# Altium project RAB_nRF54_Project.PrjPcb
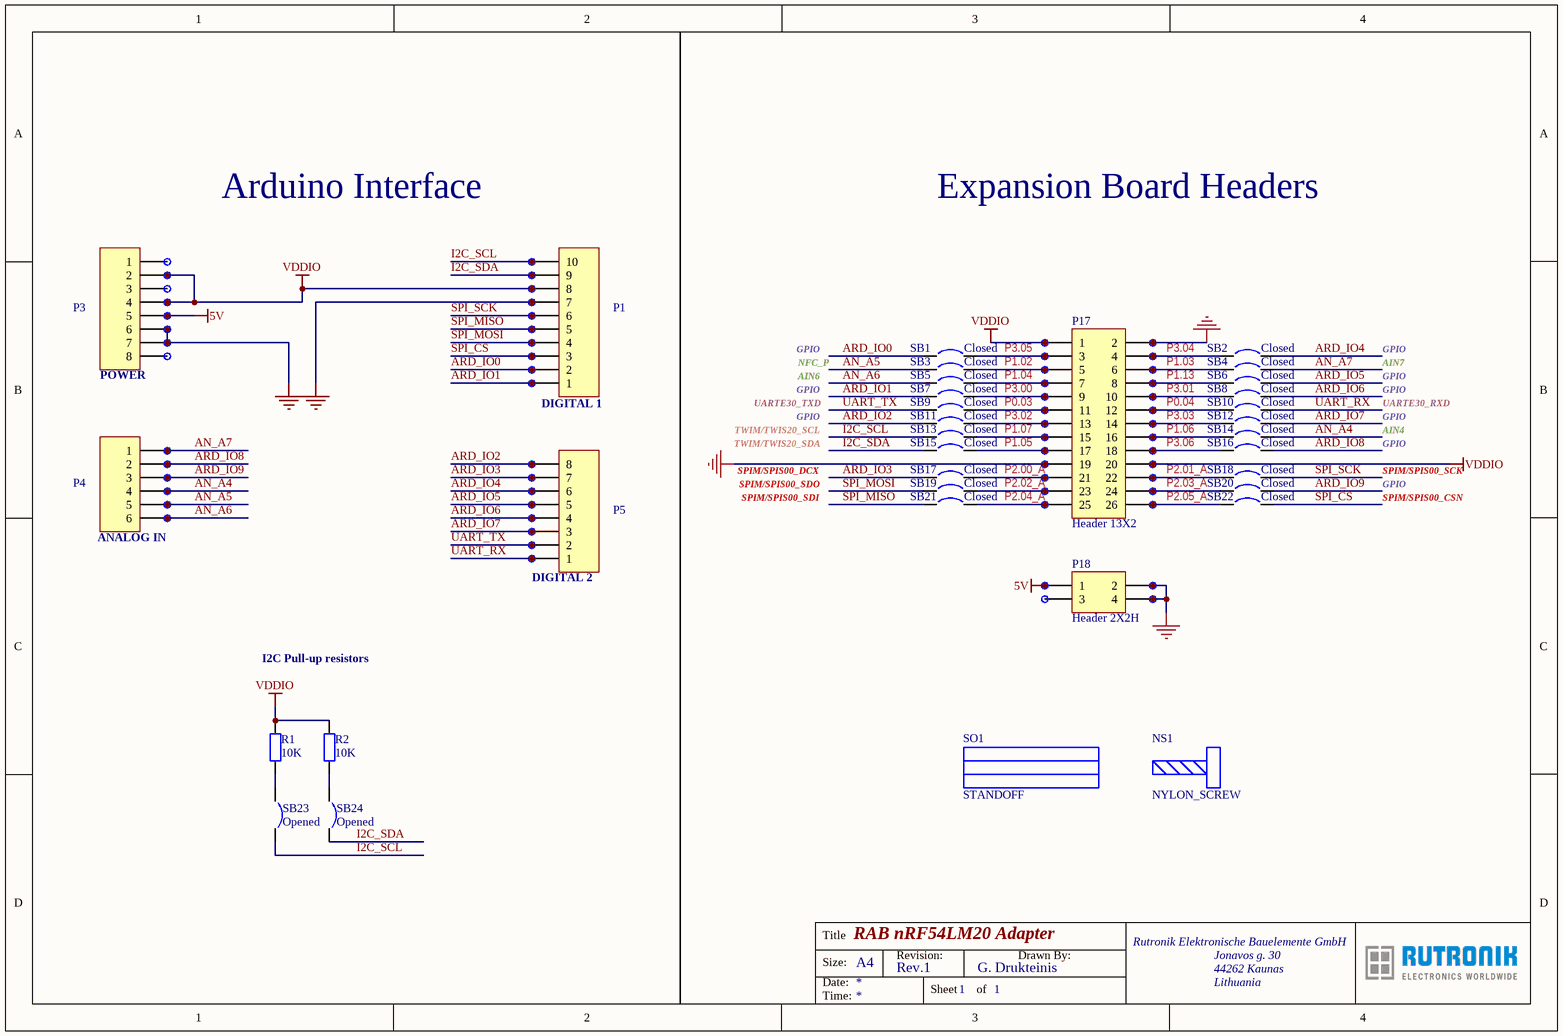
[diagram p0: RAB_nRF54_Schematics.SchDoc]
1 sheet, 96 parts. Net scope: global (net labels, ports and power ports of the same name join across sheets).
Board file: RAB-nRF54 PCB.PcbDoc

## Sheet RAB_nRF54_Schematics.SchDoc: RAB nRF54LM20 Adapter
size A4; DrawnBy: G. Drukteinis; Organization: Rutronik Elektronische Bauelemente GmbH; Address1: Jonavos g. 30; Address2: 44262 Kaunas; Address3: Lithuania; Revision: Rev.1; SheetNumber: 1; SheetTotal: 1

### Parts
J1  pin_tht  [PIN_THT]  (value not drawn)  (no BOM)
J2  pin_tht  [PIN_THT]  (value not drawn)  (no BOM)
J3  pin_tht  [PIN_THT]  (value not drawn)  (no BOM)
J4  pin_tht  [PIN_THT]  (value not drawn)  (no BOM)
J5  pin_tht  [PIN_THT]  (value not drawn)  (no BOM)
J6  pin_tht  [PIN_THT]  (value not drawn)  (no BOM)
J7  pin_tht  [PIN_THT]  (value not drawn)  (no BOM)
J8  pin_tht  [PIN_THT]  (value not drawn)  (no BOM)
J9  pin_tht  [PIN_THT]  (value not drawn)  (no BOM)
J10  pin_tht  [PIN_THT]  (value not drawn)  (no BOM)
J11  pin_tht  [PIN_THT]  (value not drawn)  (no BOM)
J12  pin_tht  [PIN_THT]  (value not drawn)  (no BOM)
J13  pin_tht  [PIN_THT]  (value not drawn)  (no BOM)
J14  pin_tht  [PIN_THT]  (value not drawn)  (no BOM)
J15  pin_tht  [PIN_THT]  (value not drawn)  (no BOM)
J16  pin_tht  [PIN_THT]  (value not drawn)  (no BOM)
J17  pin_tht  [PIN_THT]  (value not drawn)  (no BOM)
J18  pin_tht  [PIN_THT]  (value not drawn)  (no BOM)
J19  pin_tht  [PIN_THT]  (value not drawn)  (no BOM)
J20  pin_tht  [PIN_THT]  (value not drawn)  (no BOM)
J21  pin_tht  [PIN_THT]  (value not drawn)  (no BOM)
J22  pin_tht  [PIN_THT]  (value not drawn)  (no BOM)
J23  pin_tht  [PIN_THT]  (value not drawn)  (no BOM)
J24  pin_tht  [PIN_THT]  (value not drawn)  (no BOM)
J25  pin_tht  [PIN_THT]  (value not drawn)  (no BOM)
J26  pin_tht  [PIN_THT]  (value not drawn)  (no BOM)
J27  pin_tht  [PIN_THT]  (value not drawn)  (no BOM)
J28  pin_tht  [PIN_THT]  (value not drawn)  (no BOM)
J29  pin_tht  [PIN_THT]  (value not drawn)  (no BOM)
J30  pin_tht  [PIN_THT]  (value not drawn)  (no BOM)
J31  pin_tht  [PIN_THT]  (value not drawn)  (no BOM)
J32  pin_tht  [PIN_THT]  (value not drawn)  (no BOM)
J33  pin_tht  [PIN_THT]  (value not drawn)  (no BOM)
J34  pin_tht  [PIN_THT]  (value not drawn)  (no BOM)
J35  pin_tht  [PIN_THT]  (value not drawn)  (no BOM)
J36  pin_tht  [PIN_THT]  (value not drawn)  (no BOM)
J37  pin_tht  [PIN_THT]  (value not drawn)  (no BOM)
J38  pin_tht  [PIN_THT]  (value not drawn)  (no BOM)
J39  pin_tht  [PIN_THT]  (value not drawn)  (no BOM)
J40  pin_tht  [PIN_THT]  (value not drawn)  (no BOM)
J41  pin_tht  [PIN_THT]  (value not drawn)  (no BOM)
J42  pin_tht  [PIN_THT]  (value not drawn)  (no BOM)
J43  pin_tht  [PIN_THT]  (value not drawn)  (no BOM)
J44  pin_tht  [PIN_THT]  (value not drawn)  (no BOM)
J45  pin_tht  [PIN_THT]  (value not drawn)  (no BOM)
J46  pin_tht  [PIN_THT]  (value not drawn)  (no BOM)
J47  pin_tht  [PIN_THT]  (value not drawn)  (no BOM)
J48  pin_tht  [PIN_THT]  (value not drawn)  (no BOM)
J49  pin_tht  [PIN_THT]  (value not drawn)  (no BOM)
J50  pin_tht  [PIN_THT]  (value not drawn)  (no BOM)
J51  pin_tht  [PIN_THT]  (value not drawn)  (no BOM)
J52  pin_tht  [PIN_THT]  (value not drawn)  (no BOM)
J53  pin_tht  [PIN_THT]  (value not drawn)  (no BOM)
J54  pin_tht  [PIN_THT]  (value not drawn)  (no BOM)
J55  pin_tht  [PIN_THT]  (value not drawn)  (no BOM)
J56  pin_tht  [PIN_THT]  (value not drawn)  (no BOM)
J57  pin_tht  [PIN_THT]  (value not drawn)  (no BOM)
J58  pin_tht  [PIN_THT]  (value not drawn)  (no BOM)
J59  pin_tht  [PIN_THT]  (value not drawn)  (no BOM)
J60  pin_tht  [PIN_THT]  (value not drawn)  (no BOM)
J61  pin_tht  [PIN_THT]  (value not drawn)  (no BOM)
J62  pin_tht  [PIN_THT]  (value not drawn)  (no BOM)
NS1  NYLON_SCREW  [29311]
P1  DIGITAL 1  [Arduino_HDR1X10_main]
P3  POWER  [rduino_HDR1X8_main]
P4  ANALOG IN  [Arduino_HDR1X6_main]
P5  DIGITAL 2  [rduino_HDR1X8_main]
P17  Header 13X2  [RECEPTACLE_2x13_2.54_5x8.5]
P18  Header 2X2H  [RECEPTACLE_2x2_2.54_5x8.5]
R1  value 10K  [R0402]  (hidden comment: Res2)
R2  value 10K  [R0402]  (hidden comment: Res2)
SB1  Closed  [SB_0402]
SB2  Closed  [SB_0402]
SB3  Closed  [SB_0402]
SB4  Closed  [SB_0402]
SB5  Closed  [SB_0402]
SB6  Closed  [SB_0402]
SB7  Closed  [SB_0402]
SB8  Closed  [SB_0402]
SB9  Closed  [SB_0402]
SB10  Closed  [SB_0402]
SB11  Closed  [SB_0402]
SB12  Closed  [SB_0402]
SB13  Closed  [SB_0402]
SB14  Closed  [SB_0402]
SB15  Closed  [SB_0402]
SB16  Closed  [SB_0402]
SB17  Closed  [SB_0402]
SB18  Closed  [SB_0402]
SB19  Closed  [SB_0402]
SB20  Closed  [SB_0402]
SB21  Closed  [SB_0402]
SB22  Closed  [SB_0402]
SB23  Opened  [SB_0402 - open]  (no BOM)
SB24  Opened  [SB_0402 - open]  (no BOM)
SO1  STANDOFF  [24475]

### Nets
5V: J13.1 J59.1 P3.5 P18.1
GND: J8.1 J10.1 J17.1 J20.1 J36.1 J60.1 J61.1 P1.7 P3.6 P3.7 P17.2 P17.19 P18.2 P18.4
VDDIO: J3.1 J6.1 J7.1 J9.1 J37.1 P1.8 P3.2 P3.4 P17.1 P17.20 R1.2 R2.2
AN_A4: J49.1 P4.4 SB14.2
AN_A5: J51.1 P4.5 SB3.1
AN_A6: J53.1 P4.6 SB5.1
AN_A7: J42.1 P4.1 SB4.2
ARD_IO0: J28.1 P1.2 SB1.1
ARD_IO1: J31.1 P1.1 SB7.1
ARD_IO2: J46.1 P5.8 SB11.1
ARD_IO3: J48.1 P5.7 SB17.1
ARD_IO4: J50.1 P5.6 SB2.2
ARD_IO5: J52.1 P5.5 SB6.2
ARD_IO6: J54.1 P5.4 SB8.2
ARD_IO7: J55.1 P5.3 SB12.2
ARD_IO8: J45.1 P4.2 SB16.2
ARD_IO9: J47.1 P4.3 SB20.2
I2C_SCL: J2.1 P1.10 SB13.1 SB23.2
I2C_SDA: J4.1 P1.9 SB15.1 SB24.2
P0.03: J26.1 P17.11 SB9.2
P0.04: J27.1 P17.12 SB10.1
P1.02: J15.1 P17.5 SB3.2
P1.03: J16.1 P17.6 SB4.1
P1.04: J19.1 P17.7 SB5.2
P1.05: J34.1 P17.17 SB15.2
P1.06: J33.1 P17.16 SB14.1
P1.07: J32.1 P17.15 SB13.2
P1.13: J58.1 P17.8 SB6.1
P2.00_A: J38.1 P17.21 SB17.2
P2.01_A: J39.1 P17.22 SB18.1
P2.02_A: J40.1 P17.23 SB19.2
P2.03_A: J41.1 P17.24 SB20.1
P2.04_A: J43.1 P17.25 SB21.2
P2.05_A: J44.1 P17.26 SB22.1
P3.00: J22.1 P17.9 SB7.2
P3.01: J23.1 P17.10 SB8.1
P3.02: J29.1 P17.13 SB11.2
P3.03: J30.1 P17.14 SB12.1
P3.04: J12.1 P17.4 SB2.1
P3.05: J11.1 P17.3 SB1.2
P3.06: J35.1 P17.18 SB16.1
SPI_CS: J25.1 P1.3 SB22.2
SPI_MISO: J18.1 P1.5 SB21.1
SPI_MOSI: J21.1 P1.4 SB19.1
SPI_SCK: J14.1 P1.6 SB18.2
UART_RX: J57.1 P5.1 SB10.2
UART_TX: J56.1 P5.2 SB9.1
NetJ1_1: J1.1 P3.1
NetJ5_1: J5.1 P3.3
NetJ24_1: J24.1 P3.8
NetJ62_1: J62.1 P18.3
NetR1_1: R1.1 SB23.1
NetR2_1: R2.1 SB24.1

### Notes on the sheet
- Arduino Interface
- Expansion Board Headers
- GPIO
- AIN6
- NFC_P
- AIN7
- TWIM/TWIS20_SDA
- TWIM/TWIS20_SCL
- UARTE30_TXD
- AIN4
- UARTE30_RXD
- SPIM/SPIS00_DCX
- SPIM/SPIS00_SDO
- SPIM/SPIS00_SDI
- SPIM/SPIS00_SCK
- SPIM/SPIS00_CSN
- I2C Pull-up resistors

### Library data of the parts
J1-J62 = pin_tht: Through-hole pin for wire connection.
NS1 = NYLON_SCREW: M3 Pan Head Machine Screw, 6.00L P/N 29341; Manufacturer: Keystone Electronics; Specification: M3, 6mm; Rule: UNIONINDEX=0¦RULEKIND=ComponentClearance¦NETSCOPE=AnyNet¦LAYERKIND=SameLayer¦NAME=Schematic Component Clearance Constraint¦GAP=-39.3701mil¦COLLISIONCHECKMODE=3¦VERTICALGAP=100000mil¦SHOWDISTANCES=FALSE¦UNIT=Metric
P1 = Header 10: Manufacturer: Amphenol ICC; Manufacturer Part No.: 75915-310LF; Part Description: Arduino Connector; Specification: 10 pos. 2,54mm; Value: 75915-310LF
P3 P5 = Header 8: Manufacturer: Amphenol ICC; Manufacturer Part No.: 75915-308LF; Part Description: Arduino Connector; Specification: 8 pos. 2,54mm; Value: 75915-308LF
P4 = Header 6: Manufacturer: Amphenol ICC; Manufacturer Part No.: 75915-306LF; Part Description: Arduino Connector; Specification: 6 pos. 2,54mm; Value: 75915-306LF
P17 = Header 13X2: Header, 13-Pin, Dual row; Manufacturer Part No.: 87606-313LF; Manufacturer: Amphenol ICC; Part Description: nRF54 Board Connector; Specification: 13x2 pos. 2,54mm; Value: 87606-313LF
P18 = Header 2X2H: Header, 2-Pin, Dual row, Right Angle; Manufacturer Part No.: 87606-302LF; Manufacturer: Amphenol ICC; Part Description: nRF54 Board Connector; Specification: 2X2 pos. 2,54mm; Value: 87606-302LF
R1 R2 = Res2: Manufacturer: Yageo; Manufacturer Part No.: RC0402JR-1310KL; Part Description: Thick Film Resistor; Specification: 5% 0,063W
SB1-SB24 = Circuit Breaker_close: Circuit Breaker; Manufacturer: Yageo; Manufacturer Part No.: RC0402FR-070RL; Part Description: 0 Ohms Jumper; Specification: 5% 0,063W; Value: 0R
SO1 = STANDOFF: 5mm Hex Female Standoff P/N 25512; Manufacturer: Keystone Electronics; Specification: M3, 15mm; Rule: UNIONINDEX=0¦RULEKIND=ComponentClearance¦NETSCOPE=AnyNet¦LAYERKIND=SameLayer¦NAME=Schematic Component Clearance Constraint¦GAP=-39.3701mil¦COLLISIONCHECKMODE=3¦VERTICALGAP=100000mil¦SHOWDISTANCES=FALSE¦UNIT=Metric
